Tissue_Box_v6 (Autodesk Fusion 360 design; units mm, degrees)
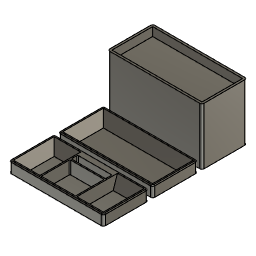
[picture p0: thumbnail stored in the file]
sketch "Sketch1" plane through (0, 0, 0) normal (0, 0, 1) x axis (1, 0, 0)
  line L1 (220, 0) -> (0, 0)
  line L2 (220, 105) -> (220, 0)
  line L3 (0, 105) -> (220, 105)
  line L4 (0, 0) -> (0, 105)
  point P1 (0, 0)
  point P2 (0, 0)
  point P3 (220, 0)
  point P5 (0, 105)
  horizontal L1
  vertical L2
  horizontal L3
  vertical L4
  coincident P1 P2
  dimension "d1" distance P2 P3 = 220
  dimension "d2" distance P2 P5 = 105
extrude "Extrude1" new body sketch "Sketch1" along normal blind 122.5 bodies "Tissue_Box_Body"
sketch "Sketch2" plane through (0, 0, 0) normal (0, 0, -1) x axis (1, 0, 0)
  line L1 (0, -105) -> (0, 0)
  line L2 (220, -105) -> (0, -105)
  line L3 (220, 0) -> (220, -105)
  line L4 (0, 0) -> (220, 0)
  line L5 (2.5, 0) -> (0, 0)
  line L6 (2.5, -2.5) -> (2.5, 0)
  line L7 (0, -2.5) -> (2.5, -2.5)
  line L8 (0, 0) -> (0, -2.5)
  line L9 (217.5, -2.5) -> (2.5, -2.5)
  line L10 (217.5, -102.5) -> (217.5, -2.5)
  line L11 (2.5, -102.5) -> (217.5, -102.5)
  line L12 (2.5, -2.5) -> (2.5, -102.5)
  point P2 (0, 0)
  point P6 (0, 0)
  point P7 (2.5, 0)
  point P9 (0, -2.5)
  point P8 (2.5, -2.5)
  point P10 (217.5, -2.5)
  point P12 (2.5, -102.5)
  horizontal L5
  vertical L6
  horizontal L7
  vertical L8
  coincident P2 P6
  horizontal L9
  vertical L10
  horizontal L11
  vertical L12
  dimension "d5" distance P6 P7 = 2.5
  dimension "d6" distance P6 P9 = 2.5
  dimension "d7" distance P8 P10 = 215
  dimension "d8" distance P8 P12 = 100
extrude "Extrude2" cut sketch "Sketch2" profile of L9 L10 L11 L12 against normal blind 120
sketch "Sketch3" plane through (0, 105, 0) normal (0, 1, 0) x axis (-1, 0, 0)
  line L1 (0, 0) -> (-220, 0)
  line L2 (0, 122.5) -> (0, 0)
  line L3 (-220, 122.5) -> (0, 122.5)
  line L4 (-220, 0) -> (-220, 122.5)
  line L5 (-180, 61.25) -> (-110, 61.25)
  line L6 (-40, 61.25) -> (-110, 61.25)
  line L7 (-110, 96.25) -> (-110, 61.25)
  line L8 (-110, 26.25) -> (-110, 61.25)
  curve K1 (-180, 61.25) -> (-180, 61.25)
  point P6 (-110, 61.25)
  point P7 (-180, 61.25)
  point P8 (-40, 61.25)
  point P9 (-110, 96.25)
  point P10 (-110, 26.25)
  vertical L7
  perpendicular L5 L7
  perpendicular L5 L8
  dimension "d13" distance P6 P7 = 70
  dimension "d14" distance P6 P8 = 70
  dimension "d15" distance P6 P9 = 35
  dimension "d16" distance P6 P10 = 35
extrude "Extrude3" cut sketch "Sketch3" profile of L5 L6 L7 L8 K1 against normal blind 10
fillet "Fillet1" radius 2.5
sketch "Sketch4" plane through (0, 0, 122.5) normal (0, 0, 1) x axis (-1, 0, 0)
  line L1 (0, 0) -> (0, -105)
  line L2 (-220, 0) -> (0, 0)
  line L3 (-220, -105) -> (-220, 0)
  line L4 (0, -105) -> (-220, -105)
  line L5 (-220, 0) -> (0, 0)
  line L6 (-220, -105) -> (-220, 0)
  line L7 (0, -105) -> (-220, -105)
  line L8 (0, 0) -> (0, -105)
  line L9 (-15, 0) -> (0, 0)
  line L10 (0, 0) -> (0, -15)
  line L11 (-205, -105) -> (-220, -105)
  line L12 (-220, -105) -> (-220, -90)
  line L13 (-205, -15) -> (-15, -15)
  line L14 (-205, -90) -> (-205, -15)
  line L15 (-15, -90) -> (-205, -90)
  line L16 (-15, -15) -> (-15, -90)
  point P3 (0, 0)
  point P6 (0, 0)
  point P5 (-220, -105)
  point P8 (-220, -105)
  point P10 (-15, 0)
  point P12 (0, -15)
  point P13 (-205, -105)
  point P15 (-220, -90)
  coincident P3 P6
  horizontal L5
  vertical L6
  horizontal L7
  vertical L8
  coincident P5 P8
  horizontal L9
  vertical L10
  horizontal L11
  vertical L12
  horizontal L13
  vertical L14
  horizontal L15
  vertical L16
  dimension "d25" distance P6 P10 = 15
  dimension "d26" distance P6 P12 = 15
  dimension "d27" distance P8 P13 = 15
  dimension "d28" distance P8 P15 = 15
extrude "Extrude4" add sketch "Sketch4" along normal blind 10
chamfer "Chamfer1" distance 10
sketch "Sketch5" plane through (0, 0, 0) normal (0, 0, 1) x axis (1, 0, 0)
  line L1 (220, -10) -> (0, -10)
  line L2 (220, -115) -> (220, -10)
  line L3 (0, -115) -> (220, -115)
  line L4 (0, -10) -> (0, -115)
  line L5 (5, -115) -> (0, -115)
  line L6 (0, -115) -> (0, -110)
  line L7 (215, -10) -> (220, -10)
  line L8 (220, -10) -> (220, -15)
  line L9 (215, -110) -> (5, -110)
  line L10 (215, -15) -> (215, -110)
  line L11 (5, -15) -> (215, -15)
  line L12 (5, -110) -> (5, -15)
  point P2 (0, -10)
  point P3 (220, -10)
  point P5 (0, -115)
  horizontal L1
  vertical L2
  horizontal L3
  vertical L4
  horizontal L5
  vertical L6
  horizontal L7
  vertical L8
  horizontal L9
  vertical L10
  horizontal L11
  vertical L12
  dimension "d32" distance P2 P3 = 220
  dimension "d33" distance P2 P5 = 105
extrude "Extrude5" new body sketch "Sketch5" along normal blind 25 bodies "Basic_Top"
extrude "Extrude6" add sketch "Sketch5" profile of L9 L10 L11 L12 against normal blind 10
chamfer "Chamfer2" distance 10
fillet "Fillet2" radius 5
fillet "Fillet3" radius 5
fillet "Fillet4" radius 5
fillet "Fillet5" radius 5
fillet "Fillet6" radius 1
fillet "Fillet7" radius 1
fillet "Fillet8" radius 1
fillet "Fillet9" radius 1
fillet "Fillet10" radius 5
fillet "Fillet11" radius 5
fillet "Fillet12" radius 5
fillet "Fillet13" radius 5
chamfer "Chamfer3" distance 2
sketch "Sketch6" plane through (0, 0, 25) normal (0, 0, 1) x axis (-1, 0, 0)
  line L1 (-215, 113) -> (-5, 113)
  line L2 (-218, 15) -> (-218, 110)
  line L3 (-5, 12) -> (-215, 12)
  line L4 (-2, 110) -> (-2, 15)
  line L5 (-15, 15) -> (-5, 15)
  line L6 (-15, 25) -> (-15, 15)
  line L7 (-5, 25) -> (-15, 25)
  line L8 (-5, 15) -> (-5, 25)
  line L9 (-205, 110) -> (-215, 110)
  line L10 (-205, 100) -> (-205, 110)
  line L11 (-215, 100) -> (-205, 100)
  line L12 (-215, 110) -> (-215, 100)
  line L13 (-205, 25) -> (-15, 25)
  line L14 (-205, 100) -> (-205, 25)
  line L15 (-15, 100) -> (-205, 100)
  line L16 (-15, 25) -> (-15, 100)
  arc A1 centre (-215, 110) radius 3 clockwise from (-218, 110) to (-215, 113)
  arc A2 centre (-215, 15) radius 3 clockwise from (-215, 12) to (-218, 15)
  arc A3 centre (-5, 15) radius 3 clockwise from (-2, 15) to (-5, 12)
  arc A4 centre (-5, 110) radius 3 clockwise from (-5, 113) to (-2, 110)
  point P11 (-5, 15)
  point P14 (-5, 15)
  point P5 (-215, 110)
  point P18 (-215, 110)
  horizontal L5
  vertical L6
  horizontal L7
  vertical L8
  coincident P11 P14
  horizontal L9
  vertical L10
  horizontal L11
  vertical L12
  coincident P5 P18
  horizontal L13
  vertical L14
  horizontal L15
  vertical L16
extrude "Extrude7" cut sketch "Sketch6" profile of L13 L14 L15 L16 against normal blind 30
copy_paste_bodies "CopyPasteBodies1"
move "Move1"
chamfer "Chamfer4" distance 10 distance 30
chamfer "Chamfer5" distance 10 distance 30
sketch "Sketch7" plane through (0, 0, 25) normal (0, 0, 1) x axis (-1, 0, 0)
  line L1 (-215, 228) -> (-5, 228)
  line L2 (-218, 130) -> (-218, 225)
  line L3 (-5, 127) -> (-215, 127)
  line L4 (-2, 225) -> (-2, 130)
  line L5 (-215, 225) -> (-215, 130)
  line L6 (-5, 225) -> (-215, 225)
  line L7 (-5, 130) -> (-5, 225)
  line L8 (-215, 130) -> (-5, 130)
  line L9 (-215, 130) -> (-5, 130)
  line L10 (-215, 225) -> (-215, 130)
  line L11 (-5, 225) -> (-215, 225)
  line L12 (-5, 130) -> (-5, 225)
  line L13 (-150, 140) -> (-70, 140)
  line L14 (-150, 155) -> (-150, 140)
  line L15 (-70, 155) -> (-150, 155)
  line L16 (-70, 140) -> (-70, 155)
  line L17 (-67, 130) -> (-70, 130)
  line L18 (-67, 225) -> (-67, 130)
  line L19 (-150, 158) -> (-70, 158)
  line L20 (-150, 225) -> (-150, 158)
  line L21 (-70, 225) -> (-150, 225)
  line L22 (-70, 158) -> (-70, 225)
  line L23 (-153, 130) -> (-150, 130)
  line L24 (-153, 225) -> (-153, 130)
  arc A1 centre (-215, 225) radius 3 clockwise from (-218, 225) to (-215, 228)
  arc A2 centre (-215, 130) radius 3 clockwise from (-215, 127) to (-218, 130)
  arc A3 centre (-5, 130) radius 3 clockwise from (-2, 130) to (-5, 127)
  arc A4 centre (-5, 225) radius 3 clockwise from (-5, 228) to (-2, 225)
  point P5 (-215, 225)
  point P16 (-215, 225)
  point P11 (-5, 130)
  point P14 (-5, 130)
  point P22 (-70, 130)
  point P23 (-150, 130)
  point P24 (-67, 130)
  point P25 (-67, 225)
  point P28 (-150, 225)
  point P30 (-153, 130)
  point P31 (-153, 225)
  point P18 (-70, 140)
  point P19 (-150, 140)
  point P21 (-70, 155)
  horizontal L9
  vertical L10
  horizontal L11
  vertical L12
  coincident P5 P16
  coincident P11 P14
  horizontal L13
  vertical L14
  horizontal L15
  vertical L16
  coincident L9 P22
  coincident L9 P23
  coincident L9 P24
  coincident L11 P25
  perpendicular L11 L18
  horizontal L19
  vertical L20
  horizontal L21
  vertical L22
  coincident L11 P28
  coincident L9 P30
  coincident L11 P31
  perpendicular L11 L24
  dimension "d71" distance P18 P19 = 80
  dimension "d72" distance P18 P21 = 15
extrude "Extrude8" add sketch "Sketch7" profile of L6 L8 L9 L11 L13 L14 L15 L16 L17 L18 L19 L20 L22 L23 L24 against normal blind 30
chamfer "Chamfer6" distance 5
fillet "Fillet14" radius 2
fillet "Fillet15" radius 2
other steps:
base_feature "Base Feature" bodies "Top_with_Phone_Holder"
named bodies: "Tissue_Box_Body", "Basic_Top", "Top_with_Phone_Holder"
